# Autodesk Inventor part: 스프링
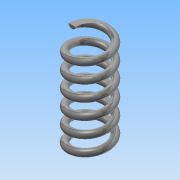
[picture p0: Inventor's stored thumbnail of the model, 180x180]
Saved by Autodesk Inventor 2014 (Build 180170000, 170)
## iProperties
Created: 2015-12
Part Number: 스프링
Material: 강철, 탄소
Document SubType Name: Modeling
Designer: imci
Density: 7.87 g/cm^3
Appearance: 반연마
Mass: 16.5234 g
Surface Area: 28.4907 cm^2
Volume: 2.09954 cm^3
Author: imci
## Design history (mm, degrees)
sketch "스케치1"
  geometry: L1 (0, 0)-(8, 0); L2 (0, 0)-(0, 42); L3 (0, 42)-(54.131, 42); C1 r 1.5 at (8, 0)
  constraints: 6 end point, 2 perpendicular, 1 centre point, 1 coincident, 1 horizontal
  dimensions: "d0" = 3 diameter of C1; "d1" = 16 diameter of C1.centre L2; "d2" = 42 distance between parallel lines of L3 L1 (derived)
feature "코일1" sketch "스케치1" pitch "d3" = 10; turns "d5" = 6; dims "d4" = 42 (= d2), "d6" = 0, angle "d7" = 90 deg, angle "d8" = 90 deg, "d9" = 0, "d10" = 0
sketch "스케치2"
  geometry: C1 r 27.666 at (0, 0); 1 further point
  constraints: 1 centre point, 1 coincident
extrude "돌출1" cut sketch "스케치2" stored distance "d11" = 0; taper "d12" = 0 deg
node "작업 평면1"
sketch "스케치3"
  geometry: C1 r 14.92 at (0, 0); 1 further point
  constraints: 1 centre point, 1 coincident
extrude "돌출2" cut sketch "스케치3" stored distance "d13" = 0; taper "d14" = 0 deg
node "솔리드1"
